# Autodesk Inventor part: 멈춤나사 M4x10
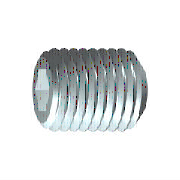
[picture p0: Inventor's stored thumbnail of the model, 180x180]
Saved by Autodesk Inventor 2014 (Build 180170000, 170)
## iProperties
Created: 2012-02
Part Number: 멈춤나사 M4x10
Material: 강철, 연강
Description: 6각 소켓 머리 없는 멈춤 나사
Document SubType Name: Modeling
Standard: KS B 1028
Designer: mduedu
Standards Organization: KS
Language: ko-KR
Size Designation: 납작점M4x10
Categories: <MemberInstance><Categories><Category DisplayName="조임쇠" InternalName="e4da775c-781d-43d5-af7c-5136215cf5a6" Mnemonic="FSTN"><Category DisplayName="볼트" InternalN
Density: 1 g/cm^3
Appearance: Steel
IsCustomPart: 1
Author: mduedu
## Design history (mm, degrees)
sketch "스케치1"
  geometry: L1 (0, 0)-(6.833, 0); L2 (10, 1.155)-(10, 2); L3 (10, 2)-(0, 2); L4 (10, 1.155)-(7.5, 1.155); L5 (7.5, 1.155)-(6.833, 0); L6 (0, -0.4)-(0, 2.4) reference; L7 (0, 2)-(0, 0)
  constraints: 13 end point, 3 parallel, 1 collinear, 1 perpendicular, 1 point on line
  dimensions: "d0" = 2.5 distance of L2.start L4.end (= INTI); "d1" = 60 deg angle of L5 L1; "d2" = 4 diameter of L3 L1 (= NND); "d3" = 2.3094 diameter of L4 L1 (= 1.1547 x SW); "d5" = 10 distance from line of L2 L3.end (= NLG)
revolve "본체" sketch "스케치1" stored, may be unused: angle "d6" = 90 deg
sketch "스케치2"
  geometry: L1 (-0.577, 1)-(0.577, 1); L2 (0.577, 1)-(1.155, 0); L3 (1.155, 0)-(0.577, -1); L4 (0.577, -1)-(-0.577, -1); L5 (-0.577, -1)-(-1.155, 0); L6 (-1.155, 0)-(-0.577, 1); A1 r 1.155 centre (0, 0) between (-0.577, 1) and (0.577, 1) reference; 2 further points
  constraints: 12 end point, 2 point on circle, 1 coincident, 1 horizontal, 11 other
extrude "슬롯" join sketch "스케치2" taper "d9" = 0 deg; stored distance "d21" = 10
workaxis "Work Axis1"
workplane "Work Plane1"
sketch "Sketch4"
  geometry: L1 (-10, -1.155)-(-7.5, -1.155) reference; L2 (-7.5, -1.155)-(-6.833, 0) reference; L3 (-6.833, 0)-(-7.5, 1.155) reference; L4 (-7.5, 1.155)-(-10, 1.155) reference; L5 (-10, 1.155)-(-10, 1.571) reference; L6 (-10, 1.571)-(-9.571, 2) reference; L7 (-9.571, 2)-(-0.429, 2) reference; L8 (-0.429, 2)-(0, 1.571) reference; L9 (0, 1.571)-(0, -1.571) reference; L10 (0, -1.571)-(-0.429, -2) reference; L11 (-0.429, -2)-(-9.571, -2) reference; L12 (-9.571, -2)-(-10, -1.571) reference; L13 (-10, -1.571)-(-10, -1.155) reference; L14 (-0.429, 2)-(1.571, 0); L15 (-0.429, -2)-(1.571, 0); 1 further point
  constraints: 4 end point, 1 parallel, 1 perpendicular
  node "Project Cut Edges1"
body "Solid1"
chamfer "모따기1" distance "d7" = 0.42941 (= -0.5 x GD1 + 0.5 x NND); stored, may be unused: angle "d8" = 45 deg (= FAWI), second distance "d29" = 0.42941 (= -0.5 x GD1 + 0.5 x NND)
feature "스레드" dims "d11" = 10 (= NLG), "d12" = 0
chamfer "모따기2" distance "d13" = 0.42941 (= -0.5 x GD1 + 0.5 x NND); stored, may be unused: angle "d14" = 45 deg (= FAWI), second distance "d30" = 0.42941 (= -0.5 x GD1 + 0.5 x NND)
other parameters: "NND" = 4 [user parameter; used in 5 equation terms], "NLG" = 10 [user parameter; used in 2 equation terms], "INTI" = 2.5 [user parameter; used in 1 equation term], "FAWI" = 45 deg [user parameter; used in 2 equation terms], "SW" = 2 [user parameter; used in 2 equation terms], "GD1" = 3.14117 (= THREADDIA - 1.2269 x PTC) [user parameter; used in 4 equation terms], "d4" = 0, "FAWI1" = 45 deg [user parameter], "d15" = 0, "d31" = 0, "GUL" = 0.42941 (= 0.61345 x PTC) [user parameter], "SPD" = 2.5 [user parameter], "TPU" = 14.28571 (computed from PTC) [user parameter], "TOA" = 30 deg [user parameter], "THREADDIA" = 4 [user parameter; used in 1 equation term], "PTC" = 0.7 [user parameter; used in 4 equation terms], "GAL" = 0.42941 (= 0.61345 x PTC) [user parameter], "E0" = 2.31 (= 1.155 x SW) [user parameter]
